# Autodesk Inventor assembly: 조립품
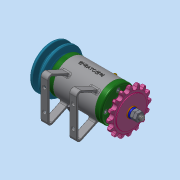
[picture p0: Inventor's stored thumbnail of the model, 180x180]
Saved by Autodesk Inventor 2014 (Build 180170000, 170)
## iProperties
Created: 2021-12
Part Number: 조립품
Document SubType Name: Assembly
Designer: dg
Author: dg
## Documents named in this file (16)
- C:\Users\dg\Desktop\711206v1015\조립품.iam
- C:\Users\dg\Desktop\711206v1015\본체.ipt
- C:\Users\dg\Desktop\711206v1015\축.ipt
- C:\Users\dg\Desktop\711206v1015\커버.ipt
- C:\Users\dg\Desktop\711206v1015\키 3 x 3.ipt
- C:\Users\dg\Desktop\711206v1015\베어링 6002.ipt
- C:\Users\dg\Desktop\711206v1015\오일 실 15 x 25 x 7.ipt
- C:\Users\dg\Desktop\711206v1015\V벨트풀리.ipt
- C:\Users\dg\Desktop\711206v1015\스프로킷.ipt
- C:\Users\dg\Desktop\711206v1015\너트 M8.ipt
- C:\Users\dg\Desktop\711206v1015\스프링와셔 8.ipt
- C:\Users\dg\Desktop\711206v1015\와셔 8 x 17.ipt
- C:\Users\dg\Desktop\711206v1015\볼트 M4 x 12.ipt
- C:\Users\dg\Desktop\711206v1015\볼트 M6 x 8.ipt
- C:\Users\dg\Desktop\711206v1015\와셔 6 x 11.5.ipt
- C:\Users\dg\Desktop\711206v1015\니플 M6 x 0.75.ipt
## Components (11 placed, 3 different names)
1. KS B 2023 6002 - 15 x 32 x 9:1
2. KS B 2023 6002 - 15 x 32 x 9:2
3. V벨트풀리:1
4. ISO 4762 M4 x 12:1
5. ISO 4762 M4 x 12:2
6. ISO 4762 M4 x 12:3
7. ISO 4762 M4 x 12:4
8. ISO 4762 M4 x 12:5
9. ISO 4762 M4 x 12:6
10. ISO 4762 M4 x 12:7
11. ISO 4762 M4 x 12:8
## Named parameters: d20_d17 = 0, d21_d18 = 0, d22_d19 = 0
